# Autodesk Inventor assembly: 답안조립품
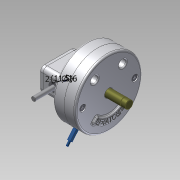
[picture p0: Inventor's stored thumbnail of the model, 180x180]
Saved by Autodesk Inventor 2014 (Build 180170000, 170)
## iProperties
Created: 2015-04
Part Number: 답안조립품
Document SubType Name: Assembly
Designer: Administrator
Author: Administrator
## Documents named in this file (15)
- C:\Documents and Settings\Administrator\바탕 화면\350406V1017\답안조립품.iam
- C:\Documents and Settings\Administrator\바탕 화면\350406V1017\본체.ipt
- C:\Documents and Settings\Administrator\바탕 화면\350406V1017\커버.ipt
- C:\Documents and Settings\Administrator\바탕 화면\350406V1017\커버2.ipt
- C:\Documents and Settings\Administrator\바탕 화면\350406V1017\베어링62_22.ipt
- C:\Documents and Settings\Administrator\바탕 화면\350406V1017\축.ipt
- C:\Documents and Settings\Administrator\바탕 화면\350406V1017\멈춤링.ipt
- C:\Documents and Settings\Administrator\바탕 화면\350406V1017\M 5 x 12.ipt
- C:\Documents and Settings\Administrator\바탕 화면\350406V1017\M 10 x 35.ipt
- C:\Documents and Settings\Administrator\바탕 화면\350406V1017\슬라이더2.ipt
- C:\Documents and Settings\Administrator\바탕 화면\350406V1017\슬라이더.ipt
- C:\Documents and Settings\Administrator\바탕 화면\350406V1017\평행핀.ipt
- C:\Documents and Settings\Administrator\바탕 화면\350406V1017\가변스프링.ipt
- C:\Documents and Settings\Administrator\바탕 화면\350406V1017\부시.ipt
- C:\Documents and Settings\Administrator\바탕 화면\350406V1017\슬라이더3.ipt
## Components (6 placed, 4 different names)
1. M 5 x 12:1
2. M 5 x 12:2
3. M 10 x 35:1
4. M 10 x 35:2
5. KS B 1320 B B 5 x  20:1
6. 가변스프링:1
